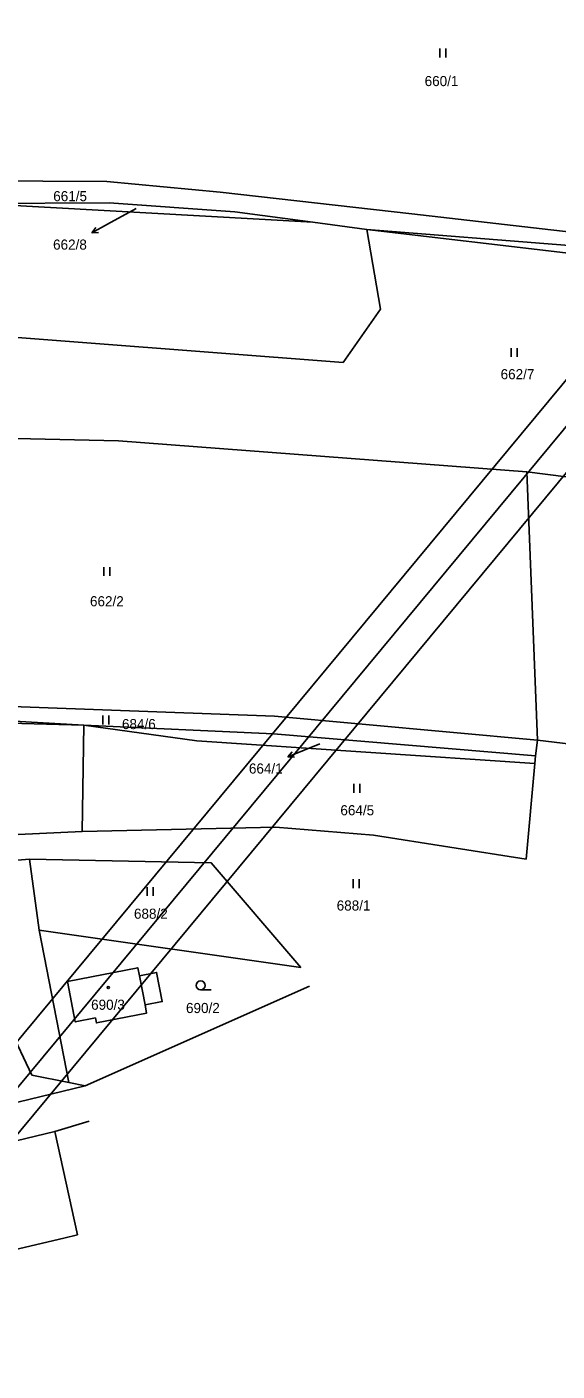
# Model space of a CAD drawing. Extents: x -738085 to -734306, y -1122197 to -1119753.
# Drawn here: x -737623.4 to -737534.1, y -1121980.5 to -1121754.3 of the extents above; entities that cross this region are included whole.
import ezdxf

# ---------------------------------------------------------------- set-up
doc = ezdxf.new("R2010")
doc.units = 0
for name, color, linetype in [('Hranice parcel', 7, 'Continuous'), ('Parcelní čísla', 7, 'Continuous'), ('Pop  PČ popisy', 7, 'Continuous'), ('Vnitřní kresba', 7, 'Continuous'), ('Vrstva 1', 7, 'Continuous'), ('Značky budov', 7, 'Continuous'), ('Značky kultur', 7, 'Continuous')]:
    doc.layers.add(name, color=color, linetype=linetype)

msp = doc.modelspace()

# ---------------------------------------------------------------- linework, layer by layer
at = {"layer": 'Hranice parcel'}
for p, q in [((-737575.2, -1121787.13), (-737631.24, -1121783.99)), ((-737575.2, -1121787.13), (-737566.13, -1121788.34)), ((-737537.39, -1121874.26), (-737539.18, -1121829.15)), ((-737675.39, -1121868.3), (-737613.79, -1121871.78)), ((-737613.79, -1121871.78), (-737667.85, -1121870.21)), ((-737614.07, -1121889.68), (-737613.79, -1121871.78)), ((-737537.39, -1121874.26), (-737537.69, -1121876.92)), ((-737528.18, -1121875.42), (-737537.39, -1121874.26)), ((-737537.81, -1121878.24), (-737539.3, -1121894.32)), ((-737537.81, -1121878.24), (-737537.69, -1121876.92)), ((-737646.13, -1121891.18), (-737614.07, -1121889.68)), ((-737621.33, -1121906.26), (-737622.97, -1121894.34)), ((-737577.27, -1121912.53), (-737621.33, -1121906.26)), ((-737616.31, -1121931.92), (-737621.33, -1121906.26)), ((-737613.56, -1121932.48), (-737575.79, -1121915.71)), ((-737613.56, -1121932.48), (-737616.31, -1121931.92)), ((-737612.92, -1121938.42), (-737618.72, -1121940.16)), ((-737618.72, -1121940.16), (-737636.36, -1121944.36)), ((-737614.86, -1121957.52), (-737618.72, -1121940.16))]:
    msp.add_line(p, q, dxfattribs=at)
for points in [[(-737650.5, -1121780.95), (-737642.35, -1121780.08), (-737609.91, -1121780.29), (-737590.85, -1121782.07), (-737558.55, -1121785.74), (-737531.67, -1121788.8), (-737479.51, -1121795.82), (-737470.66, -1121798.01)], [(-737631.24, -1121783.99), (-737609.53, -1121783.87), (-737588.35, -1121785.37), (-737575.2, -1121787.13)], [(-737692.75, -1121803.46), (-737685.54, -1121808.52), (-737663.97, -1121809.76), (-737658.72, -1121803.94), (-737570.12, -1121810.71), (-737563.82, -1121801.74), (-737566.13, -1121788.34)], [(-737470.66, -1121798.01), (-737532.01, -1121791.05), (-737566.13, -1121788.34)], [(-737566.13, -1121788.34), (-737531.67, -1121792.38), (-737480.03, -1121799.12), (-737471.73, -1121801.79)], [(-737539.18, -1121829.15), (-737607.98, -1121823.9), (-737659.96, -1121822.75), (-737691.76, -1121823.19)], [(-737483.56, -1121839.87), (-737505.12, -1121833.45), (-737539.18, -1121829.15)], [(-737679.83, -1121868.04), (-737668.67, -1121867.05), (-737581.69, -1121870.23), (-737537.39, -1121874.26)], [(-737537.69, -1121876.92), (-737581.83, -1121873.23), (-737613.79, -1121871.78)], [(-737613.79, -1121871.78), (-737594.77, -1121874.38), (-737537.81, -1121878.24)], [(-737614.07, -1121889.68), (-737581.51, -1121888.95), (-737564.99, -1121890.29), (-737539.3, -1121894.32)], [(-737622.97, -1121894.34), (-737642.85, -1121895.94), (-737645.63, -1121896.46)], [(-737622.97, -1121894.34), (-737592.34, -1121894.94), (-737577.27, -1121912.53)], [(-737603.5, -1121918.85), (-737603.23, -1121920.21), (-737611.7, -1121921.86), (-737611.86, -1121921.03), (-737615.25, -1121921.69), (-737616.57, -1121914.91), (-737604.71, -1121912.6), (-737604.45, -1121913.94), (-737601.55, -1121913.38), (-737600.6, -1121918.28), (-737603.5, -1121918.85)], [(-737616.31, -1121931.92), (-737622.56, -1121930.66), (-737626.36, -1121922.72), (-737626.81, -1121916.7), (-737650.14, -1121918.62), (-737652.36, -1121917)], [(-737652.2, -1121939.31), (-737647.46, -1121940.66), (-737613.56, -1121932.48)], [(-737636.36, -1121944.36), (-737634.66, -1121953.36), (-737634.03, -1121956.02), (-737632.68, -1121961.72), (-737627.43, -1121960.48), (-737617.19, -1121958.07), (-737614.86, -1121957.52)]]:
    msp.add_lwpolyline(points, dxfattribs=at)
at = {"layer": 'Pop  PČ popisy'}
for p, q in [((-737604.97, -1121784.8), (-737609.81, -1121787.46)), ((-737609.81, -1121787.46), (-737612.44, -1121788.92)), ((-737612.44, -1121788.92), (-737611.8, -1121787.99)), ((-737612.44, -1121788.92), (-737611.32, -1121788.87)), ((-737576.66, -1121875.95), (-737579.44, -1121877.07)), ((-737579.44, -1121877.07), (-737578.7, -1121876.24)), ((-737574.06, -1121874.9), (-737576.66, -1121875.95)), ((-737579.44, -1121877.07), (-737578.33, -1121877.16))]:
    msp.add_line(p, q, dxfattribs=at)
at = {"layer": 'Vnitřní kresba'}
msp.add_line((-737604.45, -1121913.94), (-737603.5, -1121918.85), dxfattribs=at)
at = {"layer": 'Vrstva 1'}
for points in [[(-737449.7, -1121264.8), (-737986.48, -1121910.91), (-737758.04, -1122100.69), (-737221.26, -1121454.59)], [(-737979.44, -1121910.26), (-737449.05, -1121271.84), (-737228.3, -1121455.24), (-737758.69, -1122093.65)], [(-737448.4, -1121278.88), (-737841.4, -1121751.92), (-737628.34, -1121928.94), (-737235.33, -1121455.89)]]:
    msp.add_lwpolyline(points, close=True, dxfattribs=at)
at = {"layer": 'Značky budov'}
msp.add_circle((-737609.68, -1121915.92), 0.175, dxfattribs=at)
at = {"layer": 'Značky kultur'}
for p, q in [((-737553.82, -1121759.41), (-737553.82, -1121757.91)), ((-737552.82, -1121759.41), (-737552.82, -1121757.91)), ((-737541.78, -1121809.8), (-737541.78, -1121808.3)), ((-737540.78, -1121809.8), (-737540.78, -1121808.3)), ((-737610.45, -1121846.66), (-737610.45, -1121845.16)), ((-737609.45, -1121846.66), (-737609.45, -1121845.16)), ((-737610.58, -1121871.64), (-737610.58, -1121870.14)), ((-737609.58, -1121871.64), (-737609.58, -1121870.14)), ((-737568.29, -1121883.16), (-737568.29, -1121881.66)), ((-737567.29, -1121883.16), (-737567.29, -1121881.66)), ((-737603.15, -1121900.51), (-737603.15, -1121899.01)), ((-737602.15, -1121900.51), (-737602.15, -1121899.01)), ((-737568.43, -1121899.19), (-737568.43, -1121897.69)), ((-737567.43, -1121899.19), (-737567.43, -1121897.69)), ((-737594.13, -1121916.31), (-737592.38, -1121916.31))]:
    msp.add_line(p, q, dxfattribs=at)
msp.add_circle((-737594.13, -1121915.56), 0.75, dxfattribs=at)

# ---------------------------------------------------------------- texts
at = {"layer": 'Parcelní čísla'}
for s, p in [('660/1', (-737556.38, -1121764.22)), ('661/5', (-737618.96, -1121783.59)), ('662/8', (-737618.99, -1121791.74)), ('662/7', (-737543.58, -1121813.55)), ('662/2', (-737612.77, -1121851.76)), ('684/6', (-737607.38, -1121872.43)), ('664/1', (-737585.99, -1121879.91)), ('664/5', (-737570.58, -1121886.93)), ('688/1', (-737571.2, -1121902.96)), ('688/2', (-737605.36, -1121904.34)), ('690/3', (-737612.58, -1121919.66)), ('690/2', (-737596.59, -1121920.21))]:
    msp.add_text(s, height=1.7, dxfattribs=at).set_placement(p)

doc.saveas('drawing.dxf')
